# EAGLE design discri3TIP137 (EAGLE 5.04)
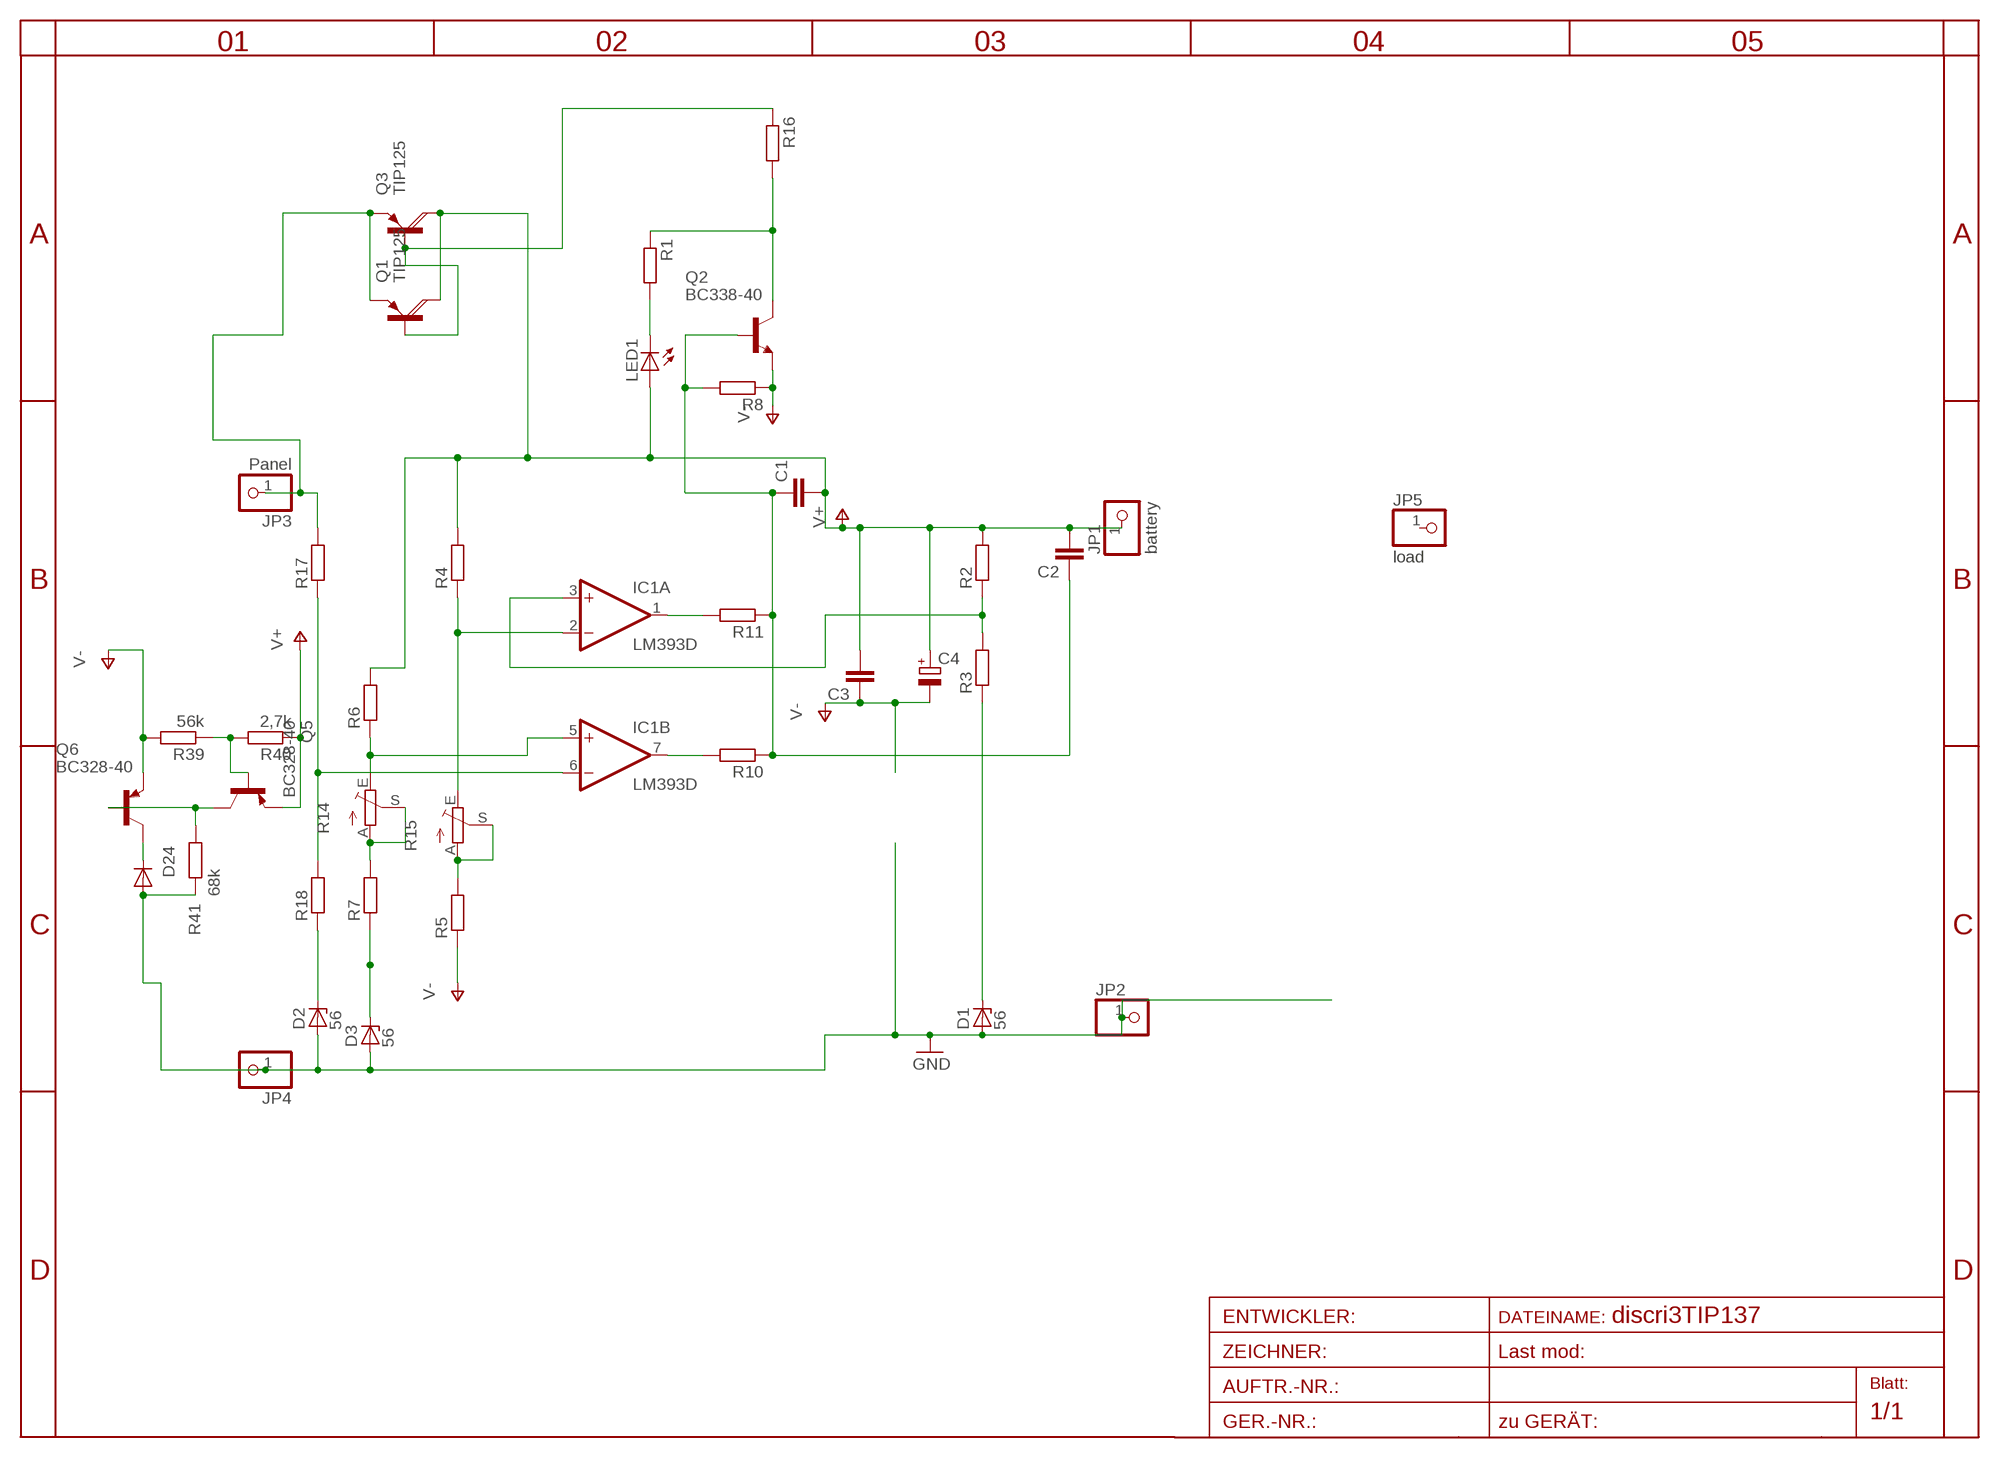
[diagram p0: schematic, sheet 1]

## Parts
C1  C-EU025-025X050  [C025-025X050]
C2  C-EU025-025X050  [C025-025X050]
C3  C-EU025-025X050  [C025-025X050]
C4  CPOL-EU5-13  [2,5-5-FLAT]
D1  56  ZENER-DIODEDO35Z10  [DO35Z10]
D2  56  ZENER-DIODEDO35Z10  [DO35Z10]
D3  56  ZENER-DIODEDO35Z10  [DO35Z10]
D24  Z20  DIODE-D-7.5  [D-7.5]
IC1  LM393D  [SO08]
JP1  battery  PINHD-1X1  [1X01]
JP2  PINHD-1X1  [1X01]
JP3  Panel  PINHD-1X1  [1X01]
JP4  PINHD-1X1  [1X01]
JP5  load  PINHD-1X1  [1X01]
LED1  LED3MM  [LED3MM]
Q1  TIP125  [TO220AH]
Q2  BC338-40  [TO92-EBC]
Q3  TIP125  [TO220AH]
Q5  BC328-40  [TO92-EBC]
Q6  BC328-40  [TO92-EBC]
R1  R-EU_0207/10  [0207/10]
R2  R-EU_0204/7  [0204/7]
R3  R-EU_0204/7  [0204/7]
R4  R-EU_0204/7  [0204/7]
R5  R-EU_0204/7  [0204/7]
R6  R-EU_0204/7  [0204/7]
R7  R-EU_0204/7  [0204/7]
R8  R-EU_0204/7  [0204/7]
R10  R-EU_0204/7  [0204/7]
R11  R-EU_0204/7  [0204/7]
R14  TRIM_EU-CA6V  [CA6V]
R15  TRIM_EU-CA6V  [CA6V]
R16  R-EU_0204/7  [0204/7]
R17  R-EU_0204/7  [0204/7]
R18  R-EU_0204/7  [0204/7]
R39  56k  R-EU_0204/7  [0204/7]
R40  2,7k  R-EU_0204/7  [0204/7]
R41  68k  R-EU_0207/10  [0207/10]

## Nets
GND: D1.A D2.A D3.A D24.A JP2.1 JP4.1 R41.2
N$1: D1.C R3.1
N$2: IC1.5(B:+IN) R6.1 R14.E
N$3: R7.2 R14.A R14.S
N$4: IC1.3(A:+IN) R2.1 R3.2
N$5: C1.1 C2.1 Q2.B R8.2 R10.1 R11.1
N$6: LED1.K(C) R1.2
N$7: IC1.7(B:OUT) R10.2
N$8: Q2.C R1.1 R16.2
N$10: IC1.6(B:-IN) R17.1 R18.2
N$11: R5.2 R15.A R15.S
N$12: IC1.2(A:-IN) R4.1 R15.E
N$13: D24.C Q6.C
N$14: IC1.1(A:OUT) R11.2
N$16: Q1.B Q3.B R16.1
N$18: D2.C R18.1
N$19: D3.C R7.1
N$38: Q5.C Q6.B R41.1
N$41: Q5.B R39.1 R40.2
PANEL: JP3.1 Q1.E Q3.E R17.2
V+: C1.2 C2.2 C3.2 C4.+ JP1.1 LED1.A Q1.C Q3.C Q5.E R2.2 R4.2 R6.2 R40.1
V-: C3.1 C4.- Q2.E Q6.E R5.1 R8.1 R39.2
Unconnected: JP5.1

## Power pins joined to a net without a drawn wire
V+: IC1.8(P:V+)
V-: IC1.4(P:V-)

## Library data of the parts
C1-C3 = rcl-2:C-EU: CAPACITOR, European symbol
C4 = rcl-2:CPOL-EU: POLARIZED CAPACITOR, European symbol
D1-D3 = diode-1:ZENER-DIODE: Z-Diode
D24 = diode-1:DIODE-: DIODE
IC1 = linear:LM393: COMPARATOR
JP1-JP5 = pinhead:PINHD-1X1: PIN HEADER
LED1 = led:LED: LED
Q1 Q3 = transistor-power:TIP125: PNP DARLINGTON TRANSISTOR
Q2 = transistor-npn:BC338*: NPN Transistor
Q5 Q6 = transistor-pnp:BC328*: PNP Transistror
R1-R8 R10 R11 R16-R18 R39-R41 = rcl-2:R-EU_: RESISTOR, European symbol
R14 R15 = pot:TRIM_EU-: POTENTIOMETER

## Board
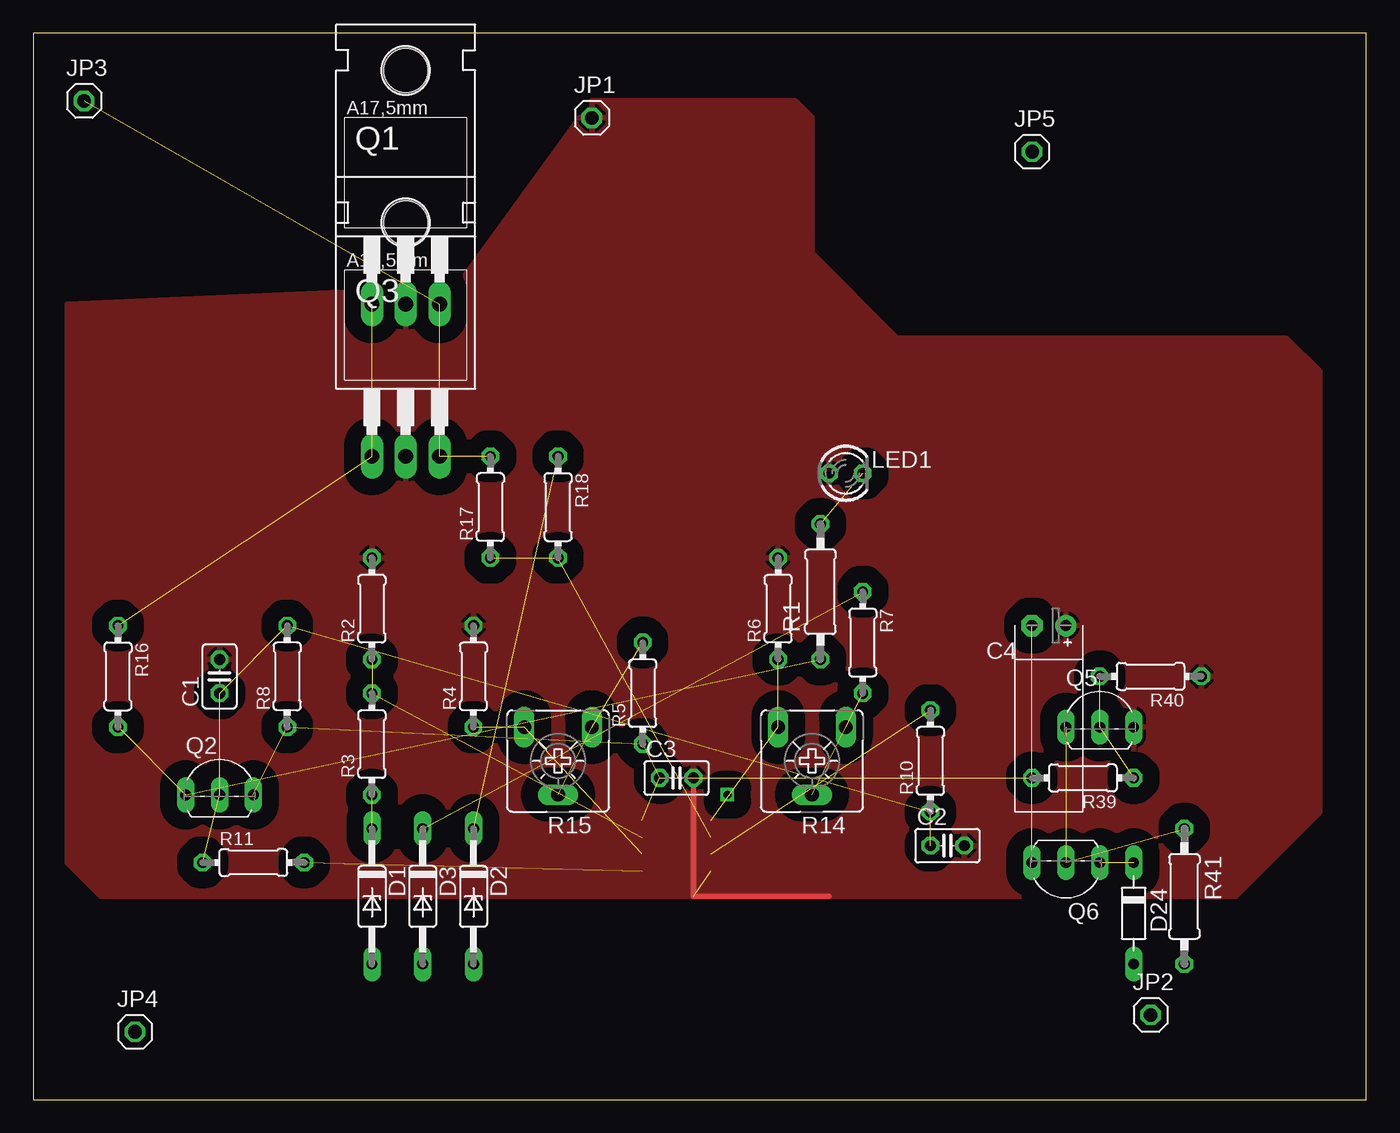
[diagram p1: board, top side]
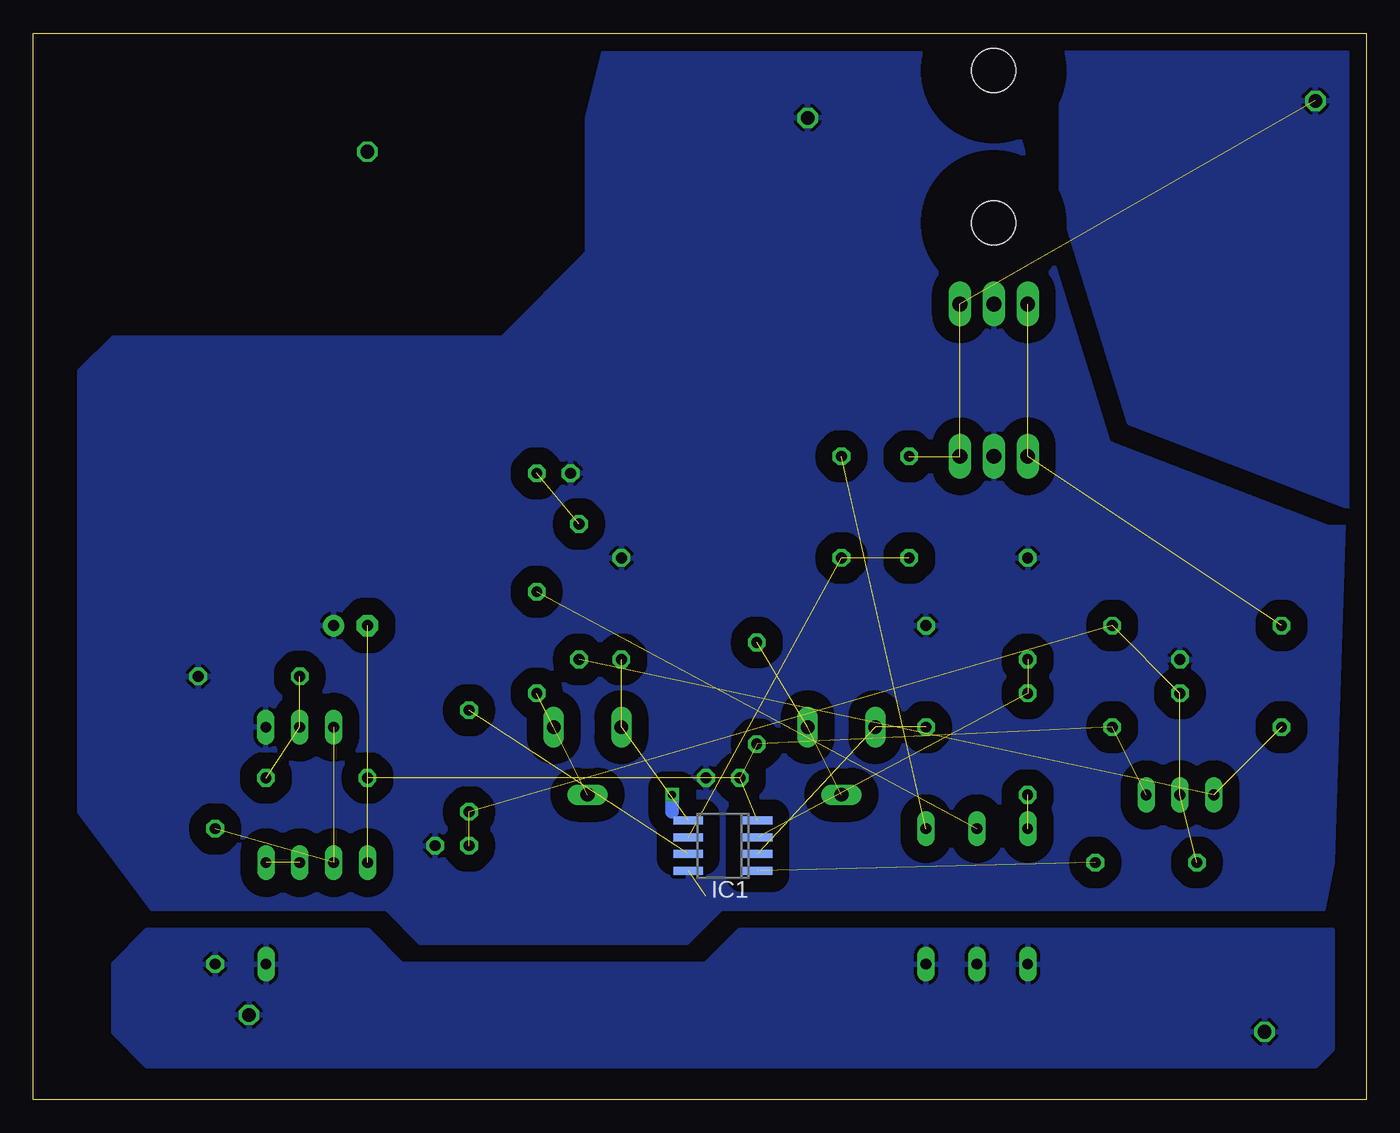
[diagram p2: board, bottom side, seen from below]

Size 100 x 80 mm. Coordinates in mm from the lower left corner, seen from the top.
Outline: 0,0 100,0 100,80 0,80 0,0
Copper layers (1*16): Top 0.035mm / dielectric 1.5mm / Bottom 0.035mm
Design rules "default": minimum track width 10mil, minimum drill 24mil, track to track 8mil, track to pad 8mil, pad to pad 8mil, via to via 8mil, smd to smd 8mil, copper to edge 40mil, drill to drill 8mil, minimum pad ring 10mil, minimum via ring 8mil, stop-mask expansion 4mil, vias tented up to drill 0mil, thermal gap 10mil

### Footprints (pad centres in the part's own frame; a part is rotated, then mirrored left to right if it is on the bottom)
C025-025X050 = drill 0.813 octagon: 1 -1.27,0; 2 1.27,0
2,5-5-FLAT = drill 0.813 pad 1.6 round: + -1.27,0 | drill 0.813 pad 1.6 octagon: - 1.27,0
DO35Z10 = drill 0.813 long: A 5.08,0; C -5.08,0
D-7.5 = drill 0.813 long: A 3.81,0; C -3.81,0
SO08 = smd 0.6 x 2.2: 1 -1.905,-2.6; 2 -0.635,-2.6; 3 0.635,-2.6; 4 1.905,-2.6; 5 1.905,2.6; 6 0.635,2.6; 7 -0.635,2.6; 8 -1.905,2.6
1X01 = drill 1.016 octagon: 1 0,0
LED3MM = drill 0.813 octagon: A -1.27,0; K 1.27,0
TO220AH = drill 1.118 long: B -2.54,-6.35; C 0,-6.35; E 2.54,-6.35 | hole 3.302: 0,11.176
TO92-EBC = drill 0.813 long: B 0,-1.27; C -2.54,-1.27; E 2.54,-1.27
0207/10 = drill 0.813 octagon: 1 -5.08,0; 2 5.08,0
0204/7 = drill 0.813 octagon: 1 -3.81,0; 2 3.81,0
CA6V = drill 1.016 long: A -2.54,-2.54; E 2.54,-2.54; S 0,2.54

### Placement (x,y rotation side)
C1  13.97,31.75 90 top
C2  68.58,19.05 0 top
C3  48.26,24.13 0 top
C4  76.2,35.56 180 top
D1  25.4,15.24 270 top
D2  33.02,15.24 270 top
D3  29.21,15.24 270 top
D24  82.55,13.97 270 top
IC1  48.26,19.05 90 bottom
JP1  41.91,73.66 0 top
JP2  83.82,6.35 0 top
JP3  3.81,74.93 0 top
JP4  7.62,5.08 0 top
JP5  74.93,71.12 0 top
LED1  60.96,46.99 0 top
Q1  27.94,66.04 0 top
Q2  13.97,24.13 0 top
Q3  27.94,54.61 0 top
Q5  80.01,29.21 0 top
Q6  77.47,16.51 180 top
R1  59.05,38.1 90 top
R2  25.4,36.83 90 top
R3  25.4,26.67 90 top
R4  33.02,31.75 90 top
R5  45.72,30.48 90 top
R6  55.88,36.83 90 top
R7  62.23,34.29 270 top
R8  19.05,31.75 90 top
R10  67.31,25.4 90 top
R11  16.51,17.78 0 top
R14  58.42,25.4 180 top
R15  39.37,25.4 180 top
R16  6.35,31.75 270 top
R17  34.29,44.45 90 top
R18  39.37,44.45 270 top
R39  78.74,24.13 180 top
R40  83.82,31.75 180 top
R41  86.36,15.24 270 top

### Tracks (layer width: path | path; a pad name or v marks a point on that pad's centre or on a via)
GND
  pour Bottom (isolate 1.27, rank 4): 2.54,12.7 46.99,12.7 49.53,10.16 72.39,10.16 74.93,12.7 91.44,12.7 93.98,10.16 93.98,5.08 91.44,2.54 3.81,2.54 2.54,3.81
N$1  (1 unrouted)
N$2  (2 unrouted)
N$3  (2 unrouted)
N$4  (2 unrouted)
N$5  (5 unrouted)
N$6  (1 unrouted)
N$7  (1 unrouted)
N$8  (2 unrouted)
N$9  (via drill 0.6)
  Bottom 1.016: 52.07,21.59 v52.07,22.86
N$10  (2 unrouted)
N$11  (2 unrouted)
N$12  (2 unrouted)
N$13  (1 unrouted)
N$14  (1 unrouted)
N$16  (2 unrouted)
N$18  (1 unrouted)
N$19  (1 unrouted)
N$38  (2 unrouted)
N$41  (2 unrouted)
PANEL  (3 unrouted)
  pour Bottom (isolate 1.27): 0,80.01 0,62.23 1.27,44.45 17.78,50.8 22.86,67.31 22.86,78.74 15.24,80.01
V+  (1 unrouted)
  Top 0.406: 59.69,15.24 49.53,15.24 C3.2
  pour Bottom (isolate 1.27, rank 5): 27.94,78.74 57.15,78.74 58.42,73.66 58.42,63.5 64.77,57.15 93.98,57.15 96.52,54.61 96.52,21.59 88.9,11.43 3.81,11.43 2.54,17.78 1.27,57.15 22.86,60.96
  pour Top (isolate 1.27, rank 5): 41.91,74.93 57.15,74.93 58.42,73.66 58.42,63.5 64.77,57.15 93.98,57.15 96.52,54.61 96.52,21.59 90.17,15.24 5.08,15.24 2.54,17.78 2.54,59.69 31.75,60.96
V-  (7 unrouted)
